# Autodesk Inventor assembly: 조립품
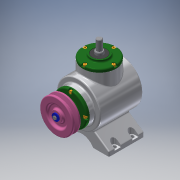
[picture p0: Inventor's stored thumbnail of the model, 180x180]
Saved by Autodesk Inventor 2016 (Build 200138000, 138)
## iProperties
Created: 2021-04
Part Number: 조립품
Material: 일반
Document SubType Name: Weldment
Designer: pc-04
Weld Material: Welded Aluminum-6061
Author: pc-04
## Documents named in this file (17)
- C:\Users\pc-04\Desktop\710407V1002\조립품.iam
- C:\Users\pc-04\Desktop\710407V1002\본채.ipt
- C:\Users\pc-04\Desktop\710407V1002\메인 베벨기어.ipt
- C:\Users\pc-04\Desktop\710407V1002\메인 축.ipt
- 메인 축.ipt
- C:\Users\pc-04\Desktop\710407V1002\서브 베벨기어.ipt
- C:\Users\pc-04\Desktop\710407V1002\서브 축.ipt
- 서브 축.ipt
- C:\Users\pc-04\Desktop\710407V1002\베어링 6203.ipt
- C:\Users\pc-04\Desktop\710407V1002\커버.ipt
- C:\Users\pc-04\Desktop\710407V1002\키 4 x 4 x 14.ipt
- C:\Users\pc-04\Desktop\710407V1002\키 5 x 5 x 14.ipt
- C:\Users\pc-04\Desktop\710407V1002\오일실 17 x 32 x 8.ipt
- C:\Users\pc-04\Desktop\710407V1002\V-벨트풀리.ipt
- C:\Users\pc-04\Desktop\710407V1002\육각볼트 M4 x 8.ipt
- C:\Users\pc-04\Desktop\710407V1002\볼트 M4 x 10.ipt
- C:\Users\pc-04\Desktop\710407V1002\와셔 4 x 16.ipt
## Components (1 placed, 1 different names)
1. V-벨트풀리:1 — 각도:4
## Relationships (1: Angle 1)
- 각도:4 [Angle]: V-벨트풀리:1
